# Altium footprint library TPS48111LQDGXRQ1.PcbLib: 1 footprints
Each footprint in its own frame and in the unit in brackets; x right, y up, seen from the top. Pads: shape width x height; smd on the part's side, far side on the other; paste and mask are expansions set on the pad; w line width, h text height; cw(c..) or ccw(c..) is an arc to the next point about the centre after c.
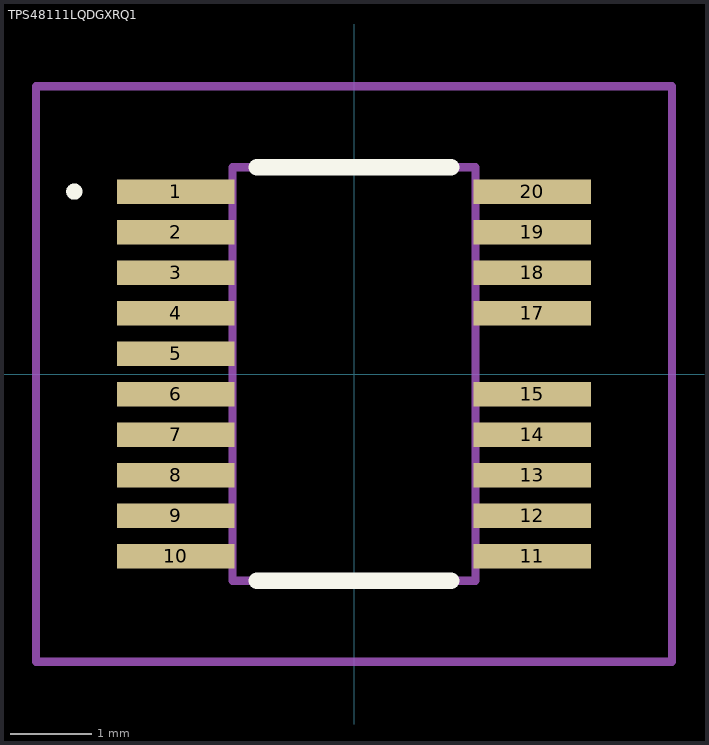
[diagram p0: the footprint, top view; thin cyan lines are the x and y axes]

## TPS48111LQDGXRQ1 [mm]
pads (19):
  rect 1.45x0.3 smd: 1(-2.2,2.25) 2(-2.2,1.75) 3(-2.2,1.25) 4(-2.2,0.75) 5(-2.2,0.25) 6(-2.2,-0.25) 7(-2.2,-0.75) 8(-2.2,-1.25) 9(-2.2,-1.75) 10(-2.2,-2.25) 11(2.2,-2.25) 12(2.2,-1.75) 13(2.2,-1.25) 14(2.2,-0.75) 15(2.2,-0.25) 17(2.2,0.75) 18(2.2,1.25) 19(2.2,1.75) 20(2.2,2.25)
Top Overlay:
  lines w0.1: -3.5,2.25 cw(c-3.45,2.25) -3.4,2.25 ; -3.5,2.25 -3.5,2.25 ; -3.5,2.25 ccw(c-3.45,2.25) -3.4,2.25 ; -3.4,2.25 -3.4,2.25
  lines w0.2: -1.2,-2.55 1.2,-2.55 ; -1.2,2.55 1.2,2.55
Mechanical 15:
  lines w0.1: -1.5,-2.55 1.5,-2.55 1.5,2.55 -1.5,2.55 -1.5,-2.55
Mechanical 20:
  lines w0.1: -3.925,-3.55 3.925,-3.55 3.925,3.55 -3.925,3.55 -3.925,-3.55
